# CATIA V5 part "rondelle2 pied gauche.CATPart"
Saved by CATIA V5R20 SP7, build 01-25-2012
Part number: rondelle 2 pied gauche
Bounding box of the stored display mesh (mm): x 9.548 to 22.172, y -79 to -65, z 51.487 to 59.353
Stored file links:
  F:\Travaux\Modélisations\CFAO_2011\CFAO_2011_MMS\CFAO_2011_MMS_DONE\CFAO_2011_MMS_jboiteux\Catia\rondelle2 pied gauche.CATPart
  U:\finthinkmotion\stepper.CATProduct
  F:\Travaux\Modélisations\CFAO_2011\CFAO_2011_MMS\CFAO_2011_MMS_DONE\CFAO_2011_MMS_jboiteux\Catia\roulement2 pied gauche.CATPart
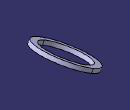
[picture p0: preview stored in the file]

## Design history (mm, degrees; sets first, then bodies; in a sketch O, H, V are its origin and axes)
Set1
  DatumSurface1: linked copy from another document
Body1 (main body)
  Sketch1 on face of DatumSurface1, origin (-19.7828, 0, 34.2647), H (0, 1, 0), V (0.866, 0, 0.5)
    projected circle E1 centre (-72, 41.4454) radius 7 from edge of DatumSurface1
    projected circle E2 centre (-72, 41.4454) radius 5.5 from edge of DatumSurface1
  Pad1: profile Sketch1, direction (-0.5, 0, 0.866), length 1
